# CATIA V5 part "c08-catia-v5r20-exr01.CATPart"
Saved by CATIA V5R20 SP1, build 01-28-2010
Part number: Part1
Bounding box of the stored display mesh (mm): x 0 to 108, y -54 to 54, z -147 to 147
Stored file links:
  D:\v5_r20\psrt_files_downloaded\c08-catia-v5r20-prt\c08-catia-v5r20-exr01.CATPart
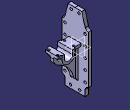
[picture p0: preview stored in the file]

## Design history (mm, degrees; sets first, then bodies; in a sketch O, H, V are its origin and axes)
Body1 (main body)
  Sketch1 on yz-plane, origin (0, 0, 0), H (0, 1, 0), V (0, 0, 1)
    point P1 (0, -147)
    line L1 (0, -147) -> (41, -147)
    point P2 (41, -147)
    line L2 (41, -147) -> (41, -122)
    point P3 (41, -122)
    arc A1 centre (54, -122) radius 13 from (41, -122) to (54, -109) cw
    point P4 (54, -122)
    point P5 (54, -109)
    line L3 (54, -109) -> (54, 87)
    point P6 (54, 87)
    arc A2 centre (54, 100) radius 13 from (54, 87) to (41.4397, 96.6475) cw
    point P7 (54, 100)
    point P8 (41.4397, 96.6475)
    line L4 (41.4397, 96.6475) -> (28, 147)
    point P9 (28, 147)
    line L5 (28, 147) -> (0, 147)
    point P10 (0, 147)
    point P12 (-41.4397, 96.6475)
    point P13 (-28, 147)
    point P14 (0, 147)
    point P15 (-54, 87)
    arc A3 centre (-54, 100) radius 13 from (-54, 87) to (-41.4397, 96.6475) ccw
    line L6 (-41.4397, 96.6475) -> (-28, 147)
    line L7 (-28, 147) -> (0, 147)
    point P16 (-54, -109)
    point P17 (-41, -122)
    arc A4 centre (-54, -122) radius 13 from (-41, -122) to (-54, -109) ccw
    line L8 (-54, -109) -> (-54, 87)
    point P19 (0, -147)
    point P20 (-41, -147)
    line L9 (0, -147) -> (-41, -147)
    line L10 (-41, -147) -> (-41, -122)
    distance L2 L10 = 82
    distance L1 P5 = 38
    length L3 = 196
    distance P6 L5 = 60
    distance P13 P9 = 56
    distance L5 H = 147
    radius A2 = 13
    radius A1 = 13
    coincidence: P1 V, P10 V, P4 L3, P7 L3, P1 P19, P10 P14
    horizontal: L1 H, L5 H
    vertical: L2 V, L3 V
    tangency: A1 L2, L4 A2
    symmetry: P8 P12 V, P9 P13 V, P10 P14 V, P6 P15 V, A2 A3 V, L4 L6 V, L5 L7 V, P5 P16 V, P3 P17 V, A1 A4 V, L3 L8 V, P1 P19 V, P2 P20 V, L1 L9 V, L2 L10 V
  Pad1: profile Sketch1, direction (1, 0, 0), length 13
  Sketch2 on zx-plane, origin (0, 0, 0), H (-1, 0, 0), V (0, 0, 1)
    line L1 (-13, 33) -> (-54, 33)
    line L2 (-54, 33) -> (-54, 17)
    arc A1 centre (-70, 17) radius 16 from (-54, 17) to (-86, 17) cw
    point P4 (-70, 17)
    line L3 (-86, 17) -> (-86, 33)
    point P6 (-86, 33)
    line L4 (-86, 33) -> (-108, 33)
    line L5 (-108, 33) -> (-108, 23)
    line L6 (-108, 23) -> (-96, 23)
    line L7 (-96, 23) -> (-96, 17)
    arc A2 centre (-70, 17) radius 26 from (-96, 17) to (-44, 17) ccw
    point P11 (-70, 17)
    line L8 (-44, 17) -> (-44, 23)
    line L9 (-44, 23) -> (-13, 23)
    line L10 (-13, 23) -> (-13, 33)
    reference projected line E1 (-13, -109) -> (-13, 87) from edge [face of Pad1 | face of Pad1]
    reference projected line E2 (0, -147) -> (-13, -147) from edge [face of Pad1 | face of Pad1]
    distance L10 L5 = 95
    radius A1 = 16
    distance A1 A2 = 10
    length L5 = 10
    length L10 = 10
    length L2 = 16
    distance P11 L5 = 38
    distance L1 E2 = 180
    horizontal: L1 H, L4 H, L6 H, L9 H
    vertical: L2 V, L5 V, L7 V, L10 V, L3 V, L8 V
    tangency: A1 L2, L3 A1, A2 L7, L8 A2
    coincidence: P6 L1, P11 P4, L10 E1
  Pad2: profile Sketch2, direction (0, 1, 0), length 30, mirrored extent
  Sketch3 on face of Pad2, origin (0, 0, 33), H (1, 0, 0), V (0, 1, 0)
    line L1 (96, 30) -> (108, 30)
    line L2 (108, 30) -> (108, 25)
    line L3 (108, 25) -> (96, 25)
    line L4 (96, 25) -> (96, 30)
    reference projected line E1 (86, 30) -> (108, 30) from edge [face of Pad2 | face of Pad2]
    reference projected line E2 (108, -30) -> (108, 30) from edge [face of Pad2 | face of Pad2]
    line L5 (13, 30) -> (44, 30)
    line L6 (44, 30) -> (44, 25)
    line L7 (44, 25) -> (13, 25)
    line L8 (13, 25) -> (13, 30)
    reference projected line E3 (13, 28) -> (13, 0) from edge [face of Pad1 | face of Pad1]
    reference projected line E4 (13, 30) -> (54, 30) from edge [face of Pad2 | face of Pad2]
    reference projected line E5 (54, -30) -> (54, 30) from edge [face of Pad2 | face of Pad2]
    reference projected line E6 (86, -30) -> (86, 30) from edge [face of Pad2 | face of Pad2]
    length L2 = 5
    length L6 = 5
    distance E5 L6 = 10
    distance L4 E6 = 10
    horizontal: L1 H, L3 H, L5 H, L7 H
    vertical: L2 V, L4 V, L6 V, L8 V
    coincidence: L1 E1, L2 E2, L8 E3, L5 E4
  Pocket1: profile Sketch3, direction (0, 0, -1), length 10
  Fillet1: radius 5, on 2 edges
  Mirror1: of Pocket1, Sketch3, Fillet1, about zx-plane
  Sketch4 on zx-plane, origin (0, 0, 0), H (-1, 0, 0), V (0, 0, 1)
    point P1 (-108, 23)
    line L1 (-108, 23) -> (-108, 17)
    arc A1 centre (-70, 17) radius 38 from (-108, 17) to (-84.7594, -18.0166) ccw
    arc A2 centre (-123.6, -110.1654) radius 100 from (-84.7594, -18.0166) to (-25.7239, -89.665) cw
    arc A3 centre (-13, -87) radius 13 from (-25.7239, -89.665) to (-13, -100) ccw
    point P7 (-13, -87)
    point P8 (-13, -100)
    reference projected line E1 (-13, -109) -> (-13, 87) from edge [face of Pad1 | face of Pad1]
    reference projected line E2 (-108, 33) -> (-108, 23) from edge [face of Pad2 | face of Pocket1]
    reference projected line E3 (-96, 23) -> (-108, 23) from edge [face of Pocket1 | face of Pad2]
    reference projected arc E4 centre (-70, 17) radius 26 from (-96, 17) to (-44, 17) ccw from edge [face of Pad2 | face of Pad2]
    reference projected line E5 (-13, -109) -> (-13, 87) from edge [face of Pad1 | face of Pad1]
    reference projected line E6 (-13, 33) -> (-39, 33) from edge [face of Pad2 | face of Pocket1]
    radius A2 = 100
    radius A3 = 13
    distance P7 E6 = 120
    vertical: L1 V
    tangency: A1 L1, A2 A1, A3 A2
    coincidence: P8 E1, L1 E2, P1 E3, P7 E5
    concentricity: A1 E4
  Stiffener1: ThicknessValue 13, ExtendedProfile Sketch4, ThicknessTop 0
  Fillet2: radius 5, on edge [face of Stiffener1 | face of Pad2]; edge [face of Pad2 | face of Stiffener1]; 3 edges
  Sketch5 on face of Mirror1, origin (13, -31.1023, -134.1999), H (0, 1, 0), V (0, 0, 1)
    point P1 (12.1023, 0.1999)
    reference projected line E1 (-9.8977, -12.8001) -> (31.1023, -12.8001) from edge [face of Pad1 | face of Pad1]
    reference projected line E2 (-9.8977, 12.1999) -> (-9.8977, -12.8001) from edge [face of Pad1 | face of Pad1]
    distance P1 E1 = 13
    distance E2 P1 = 22
  Hole1: placed by Sketch5, at (13, -19, -134) direction (-1, 0, 0), diameter 10, through (limit type 3)
  Sketch6 on face of Mirror1, origin (13, 0, 0), H (0, 1, 0), V (0, 0, 1)
    point P1 (19, -134)
    point P2 (41, -96)
    point P3 (41, -53)
    point P4 (41, -11)
    point P5 (41, 31)
    point P6 (41, 74)
    point P7 (16, 134)
    point P8 (0, 0)
    point P9 (-41, -96)
    point P10 (-41, -53)
    point P11 (-41, -11)
    point P12 (-41, 31)
    point P13 (-41, 74)
    point P14 (-16, 134)
    reference projected point E1 (54, 87) from vertex [face of Pad1 | face of Pad1 | face of Pad1]
    reference projected point E2 (54, 87) from vertex [face of Pad1 | face of Pad1 | face of Pad1]
    axis line L1 (41, 74) -> (41, -87.5254)
    reference projected point E3 (54, -109) from vertex [face of Pad1 | face of Pad1 | face of Pad1]
    reference projected line E4 (28, 147) -> (0, 147) from edge of Pad1
    reference projected line E5 (0, -147) -> (41, -147) from edge [face of Pad1 | face of Pad1]
    reference projected line E6 (41, -147) -> (41, -122) from edge [face of Pad1 | face of Pad1]
    distance P7 P14 = 32
    distance P6 E1 V = 13
    distance P5 P6 = 43
    distance P6 E2 H = 13
    distance E3 P2 V = 13
    distance P3 P2 = 43
    distance P4 P5 = 42
    distance P7 E4 = 13
    distance P1 E5 = 13
    distance P1 E6 = 22
    symmetry: O P8 V, P2 P9 V, P3 P10 V, P4 P11 V, P5 P12 V, P6 P13 V, P7 P14 V
    coincidence: L1 P2, P5 L1, P4 L1, P3 L1
    vertical: L1 V
  UserPattern1: of Hole1, copies 14, at the points of Sketch6
  Sketch7 on face of Pad2, origin (91.4506, 2.7036, 33), H (1, 0, 0), V (0, 1, 0)
    point P1 (10.5494, -20.7036)
    reference projected line E1 (-5.4506, -32.7036) -> (16.5494, -32.7036) from edge [face of Pad2 | face of Pad2]
    reference projected line E2 (16.5494, -27.7036) -> (16.5494, 22.2964) from edge [face of Pad2 | face of Pad2]
    distance P1 E1 = 12
    distance E2 P1 = 6
  Hole2: placed by Sketch7, at (102, -18, 33) direction (0, 0, -1), diameter 8, through (limit type 3)
  RectPattern1: of Hole2, direction 1 instances 2, spacing 65, along edge [face of Pad2 | face of Pad2] reversed, direction 2 instances 2, spacing 36, along edge of Stiffener1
